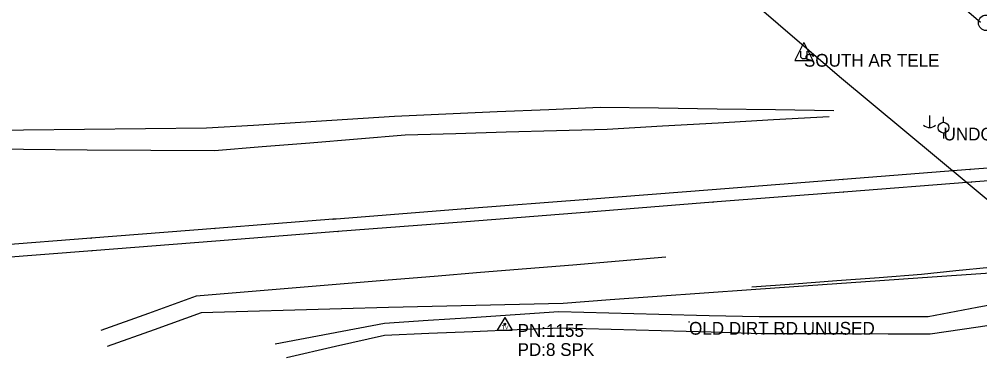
# Model space of a CAD drawing. Extents: x 878399 to 889864, y 1564003 to 1567413.
# Drawn here: x 884308.5 to 884685, y 1565399.8 to 1565532.7 of the extents above; entities that cross this region are included whole.
import ezdxf

# ---------------------------------------------------------------- set-up
doc = ezdxf.new("R2010")
doc.units = 0
for name, color, linetype in [('S_DITCHLINE', 7, 'Continuous'), ('S_EDGE_CONCRETE', 7, 'Continuous'), ('S_FIBER_OPTIC_CABLE', 7, 'Continuous'), ('S_MSC_PT_SYM', 7, 'Continuous'), ('S_RAILROAD', 7, 'Continuous'), ('S_SECONDARY_CTL', 7, 'Continuous'), ('S_SECONDARY_CTL_ANNOT', 7, 'Continuous'), ('S_STORM_SEWER', 7, 'Continuous'), ('S_SURVEY_TEXT_ANNOT', 7, 'Continuous'), ('S_TELEPHONE_UTILITIES', 7, 'Continuous'), ('S_TELEPHONE_UTILITIES_ANNOT', 7, 'Continuous'), ('S_TRAILS', 7, 'Continuous'), ('S_UTILITY_POLE', 7, 'Continuous'), ('S_UTILITY_POLE_ANNOT', 7, 'Continuous'), ('S_UTL_PT_SYM', 7, 'Continuous')]:
    doc.layers.add(name, color=color, linetype=linetype)

msp = doc.modelspace()

# ---------------------------------------------------------------- linework, layer by layer
at = {"layer": 'S_DITCHLINE'}
for points in [[(884627.86, 1565496.72), (884604.94, 1565497.05), (884582.03, 1565497.38), (884559.11, 1565497.71), (884536.19, 1565498.04), (884516.04, 1565497.15), (884495.89, 1565496.27), (884475.74, 1565495.38), (884455.59, 1565494.49), (884437.16, 1565493.33), (884418.73, 1565492.17), (884400.3, 1565491.02), (884381.86, 1565489.86), (884357.97, 1565489.6), (884334.07, 1565489.34), (884310.17, 1565489.08), (884286.28, 1565488.82)], [(884625.97, 1565494.43), (884604.21, 1565493.18), (884582.45, 1565491.93), (884560.69, 1565490.67), (884538.93, 1565489.42), (884519.14, 1565488.86), (884499.35, 1565488.29), (884479.56, 1565487.72), (884459.77, 1565487.15), (884441.06, 1565485.61), (884422.36, 1565484.08), (884403.66, 1565482.54), (884384.95, 1565481.01), (884360, 1565481.18), (884335.05, 1565481.35), (884310.1, 1565481.52), (884285.15, 1565481.69)], [(884561.94, 1565439.36), (884543.68, 1565437.8), (884525.43, 1565436.23), (884507.33, 1565434.74), (884489.23, 1565433.25), (884471.14, 1565431.75), (884453.04, 1565430.26), (884434.25, 1565428.7), (884415.46, 1565427.14), (884396.67, 1565425.58), (884377.87, 1565424.03), (884359.19, 1565417.28), (884340.5, 1565410.54)], [(884715.98, 1565438.16), (884702.53, 1565436.73), (884689.09, 1565435.31), (884675.64, 1565433.89), (884662.2, 1565432.47), (884645.57, 1565431.23), (884628.93, 1565429.99), (884612.3, 1565428.74), (884595.67, 1565427.5)], [(884715.76, 1565434.83), (884702.47, 1565433.93), (884689.18, 1565433.03), (884675.89, 1565432.13), (884662.6, 1565431.23), (884645.79, 1565430.06), (884628.99, 1565428.9), (884612.18, 1565427.73), (884595.37, 1565426.56), (884576.96, 1565425.22), (884558.55, 1565423.88), (884540.14, 1565422.54), (884521.73, 1565421.2), (884504.59, 1565420.79), (884487.45, 1565420.37), (884470.31, 1565419.96), (884453.17, 1565419.55), (884434.83, 1565419.04), (884416.48, 1565418.52), (884398.13, 1565418.01), (884379.78, 1565417.5), (884361.38, 1565410.86), (884342.98, 1565404.22)]]:
    msp.add_lwpolyline(points, dxfattribs=at)
at = {"layer": 'S_EDGE_CONCRETE'}
msp.add_lwpolyline([(884514.23, 1565678.05), (884518.85, 1565672.72), (884541.36, 1565653.58), (884579.74, 1565621.54), (884617.9, 1565589.19), (884653.7, 1565558.74), (884685.33, 1565531.53)], dxfattribs=at)
at = {"layer": 'S_FIBER_OPTIC_CABLE'}
for p, q in [((884630.03, 1565510.1), (884585.04, 1565548.94)), ((884746.2, 1565413.17), (884630.03, 1565510.1))]:
    msp.add_line(p, q, dxfattribs=at)
at = {"layer": 'S_MSC_PT_SYM'}
for points in [[(884681.18, 1565473.66), (884681.18, 1565473.71), (884681.18, 1565473.66), (884681.13, 1565473.66), (884681.18, 1565473.66), (884681.18, 1565473.61), (884681.18, 1565473.66), (884681.23, 1565473.66)], [(884631.44, 1565469.83), (884631.44, 1565469.88), (884631.44, 1565469.83), (884631.39, 1565469.83), (884631.44, 1565469.83), (884631.44, 1565469.78), (884631.44, 1565469.83), (884631.49, 1565469.83)], [(884681.7, 1565468.75), (884681.7, 1565468.8), (884681.7, 1565468.75), (884681.65, 1565468.75), (884681.7, 1565468.75), (884681.7, 1565468.7), (884681.7, 1565468.75), (884681.75, 1565468.75)], [(884580.12, 1565465.78), (884580.12, 1565465.83), (884580.12, 1565465.78), (884580.07, 1565465.78), (884580.12, 1565465.78), (884580.12, 1565465.73), (884580.12, 1565465.78), (884580.17, 1565465.78)], [(884631.58, 1565464.81), (884631.58, 1565464.86), (884631.58, 1565464.81), (884631.53, 1565464.81), (884631.58, 1565464.81), (884631.58, 1565464.76), (884631.58, 1565464.81), (884631.63, 1565464.81)], [(884531.35, 1565461.94), (884531.35, 1565461.99), (884531.35, 1565461.94), (884531.3, 1565461.94), (884531.35, 1565461.94), (884531.35, 1565461.89), (884531.35, 1565461.94), (884531.4, 1565461.94)], [(884580.41, 1565460.85), (884580.41, 1565460.9), (884580.41, 1565460.85), (884580.36, 1565460.85), (884580.41, 1565460.85), (884580.41, 1565460.8), (884580.41, 1565460.85), (884580.46, 1565460.85)], [(884483.47, 1565458.22), (884483.47, 1565458.27), (884483.47, 1565458.22), (884483.42, 1565458.22), (884483.47, 1565458.22), (884483.47, 1565458.17), (884483.47, 1565458.22), (884483.52, 1565458.22)], [(884531.83, 1565457), (884531.83, 1565457.05), (884531.83, 1565457), (884531.78, 1565457), (884531.83, 1565457), (884531.83, 1565456.95), (884531.83, 1565457), (884531.88, 1565457)], [(884431.48, 1565454.22), (884431.48, 1565454.27), (884431.48, 1565454.22), (884431.43, 1565454.22), (884431.48, 1565454.22), (884431.48, 1565454.17), (884431.48, 1565454.22), (884431.53, 1565454.22)], [(884432.72, 1565454.26), (884432.72, 1565454.31), (884432.72, 1565454.26), (884432.67, 1565454.26), (884432.72, 1565454.26), (884432.72, 1565454.21), (884432.72, 1565454.26), (884432.77, 1565454.26)], [(884483.68, 1565453.24), (884483.68, 1565453.29), (884483.68, 1565453.24), (884483.63, 1565453.24), (884483.68, 1565453.24), (884483.68, 1565453.19), (884483.68, 1565453.24), (884483.73, 1565453.24)], [(884385.22, 1565450.59), (884385.22, 1565450.64), (884385.22, 1565450.59), (884385.17, 1565450.59), (884385.22, 1565450.59), (884385.22, 1565450.54), (884385.22, 1565450.59), (884385.27, 1565450.59)], [(884433.43, 1565449.32), (884433.43, 1565449.37), (884433.43, 1565449.32), (884433.38, 1565449.32), (884433.43, 1565449.32), (884433.43, 1565449.27), (884433.43, 1565449.32), (884433.48, 1565449.32)], [(884336.64, 1565446.73), (884336.64, 1565446.78), (884336.64, 1565446.73), (884336.59, 1565446.73), (884336.64, 1565446.73), (884336.64, 1565446.68), (884336.64, 1565446.73), (884336.69, 1565446.73)], [(884385.55, 1565445.6), (884385.55, 1565445.65), (884385.55, 1565445.6), (884385.5, 1565445.6), (884385.55, 1565445.6), (884385.55, 1565445.55), (884385.55, 1565445.6), (884385.6, 1565445.6)], [(884337, 1565441.81), (884337, 1565441.86), (884337, 1565441.81), (884336.95, 1565441.81), (884337, 1565441.81), (884337, 1565441.76), (884337, 1565441.81), (884337.05, 1565441.81)], [(884571.06, 1565413.9), (884571.06, 1565413.95), (884571.06, 1565413.9), (884571.01, 1565413.9), (884571.06, 1565413.9), (884571.06, 1565413.85), (884571.06, 1565413.9), (884571.11, 1565413.9)]]:
    msp.add_lwpolyline(points, dxfattribs=at)
at = {"layer": 'S_RAILROAD'}
for p, q in [((884717.39, 1565476.51), (884681.18, 1565473.66)), ((884681.18, 1565473.66), (884631.44, 1565469.83)), ((884717.78, 1565471.58), (884681.7, 1565468.75)), ((884631.44, 1565469.83), (884580.12, 1565465.78)), ((884681.7, 1565468.75), (884631.58, 1565464.81)), ((884580.12, 1565465.78), (884531.35, 1565461.94)), ((884631.58, 1565464.81), (884580.41, 1565460.85)), ((884531.35, 1565461.94), (884483.47, 1565458.22)), ((884580.41, 1565460.85), (884531.83, 1565457)), ((884483.47, 1565458.22), (884432.72, 1565454.26)), ((884531.83, 1565457), (884483.68, 1565453.24)), ((884431.48, 1565454.22), (884385.22, 1565450.59)), ((884432.72, 1565454.26), (884431.48, 1565454.22)), ((884483.68, 1565453.24), (884433.43, 1565449.32)), ((884385.22, 1565450.59), (884336.64, 1565446.73)), ((884433.43, 1565449.32), (884385.55, 1565445.6)), ((884336.64, 1565446.73), (884287.66, 1565442.92)), ((884385.55, 1565445.6), (884337, 1565441.81)), ((884337, 1565441.81), (884288.4, 1565438.05))]:
    msp.add_line(p, q, dxfattribs=at)
at = {"layer": 'S_SECONDARY_CTL'}
for p, q in [((884498.82, 1565415.67), (884495.81, 1565410.71)), ((884498.82, 1565415.67), (884501.77, 1565410.71)), ((884495.81, 1565410.71), (884501.77, 1565410.71))]:
    msp.add_line(p, q, dxfattribs=at)
for radius in [0.311, 0.183, 0.103]:
    msp.add_circle((884498.82, 1565413.06), radius, dxfattribs=at)
at = {"layer": 'S_STORM_SEWER'}
msp.add_circle((884687.54, 1565531.25), 3.05, dxfattribs=at)
at = {"layer": 'S_TELEPHONE_UTILITIES'}
for p, q in [((884670.79, 1565492.19), (884670.79, 1565494.32)), ((884670.79, 1565487.97), (884670.79, 1565485.91))]:
    msp.add_line(p, q, dxfattribs=at)
msp.add_circle((884670.81, 1565490.11), 2.11, dxfattribs=at)
at = {"layer": 'S_TRAILS'}
for points in [[(884703.25, 1565423.08), (884684.03, 1565419.52), (884664.82, 1565415.97), (884648.24, 1565415.94), (884631.66, 1565415.92), (884615.09, 1565415.89), (884598.51, 1565415.87), (884578.88, 1565416.36), (884559.25, 1565416.85), (884539.62, 1565417.34), (884519.99, 1565417.83), (884502.9, 1565416.7), (884485.81, 1565415.57), (884468.72, 1565414.44), (884451.64, 1565413.31), (884430.23, 1565409.24), (884408.83, 1565405.18)], [(884703.28, 1565414.74), (884684.46, 1565411.91), (884665.64, 1565409.08), (884649.06, 1565409.13), (884632.48, 1565409.18), (884615.9, 1565409.23), (884599.32, 1565409.28), (884579.72, 1565409.84), (884560.12, 1565410.39), (884540.53, 1565410.94), (884520.93, 1565411.49), (884503.63, 1565410.76), (884486.32, 1565410.03), (884469.02, 1565409.31), (884451.72, 1565408.58), (884432.46, 1565404.21), (884413.21, 1565399.84)]]:
    msp.add_lwpolyline(points, dxfattribs=at)
at = {"layer": 'S_UTILITY_POLE'}
for p, q in [((884616.1, 1565523.57), (884612.58, 1565516.48)), ((884616.1, 1565523.57), (884619.59, 1565516.48)), ((884614.9, 1565517.72), (884614.9, 1565520.16)), ((884617.27, 1565520.16), (884617.27, 1565517.72)), ((884612.58, 1565516.48), (884619.59, 1565516.48)), ((884615.52, 1565517.06), (884614.9, 1565517.72)), ((884616.72, 1565517.06), (884615.52, 1565517.06)), ((884617.27, 1565517.72), (884616.72, 1565517.06)), ((884665.31, 1565494.86), (884665.31, 1565490.13))]:
    msp.add_line(p, q, dxfattribs=at)
msp.add_arc((884665.37, 1565493.56), 3.41, 226.3972, 313.6028, dxfattribs=at)
at = {"layer": 'S_UTL_PT_SYM'}
msp.add_lwpolyline([(884630.03, 1565510.1), (884630.03, 1565510.15), (884630.03, 1565510.1), (884629.98, 1565510.1), (884630.03, 1565510.1), (884630.03, 1565510.05), (884630.03, 1565510.1), (884630.08, 1565510.1)], dxfattribs=at)

# ---------------------------------------------------------------- texts
at = {"layer": 'S_SECONDARY_CTL'}
msp.add_text('TV', height=1.5, rotation=360, dxfattribs=at).set_placement((884497.62, 1565411.04))
at = {"layer": 'S_SECONDARY_CTL_ANNOT'}
for s, p in [('PN:1155', (884503.82, 1565408.06)), ('PD:8 SPK', (884503.82, 1565400.56))]:
    msp.add_text(s, height=5, dxfattribs=at).set_placement(p)
at = {"layer": 'S_SURVEY_TEXT_ANNOT'}
msp.add_text('OLD DIRT RD UNUSED', height=5, dxfattribs=at).set_placement((884571.06, 1565408.9))
at = {"layer": 'S_TELEPHONE_UTILITIES_ANNOT'}
msp.add_text('UNDGRND CABLE', height=5, dxfattribs=at).set_placement((884670.81, 1565485.11))
at = {"layer": 'S_UTILITY_POLE_ANNOT'}
msp.add_text('SOUTH AR TELE', height=5, dxfattribs=at).set_placement((884616.1, 1565514.04))

doc.saveas('drawing.dxf')
